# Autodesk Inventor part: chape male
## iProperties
Created: 2009-03
Part Number: chape male
Document SubType Name: Modeling
Designer: Ordi1
Author: Ordi1
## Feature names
1. Extrusion1
2. Chanfrein1 [Chamfer]
3. Extrusion2
4. Perçage1 [Hole]
